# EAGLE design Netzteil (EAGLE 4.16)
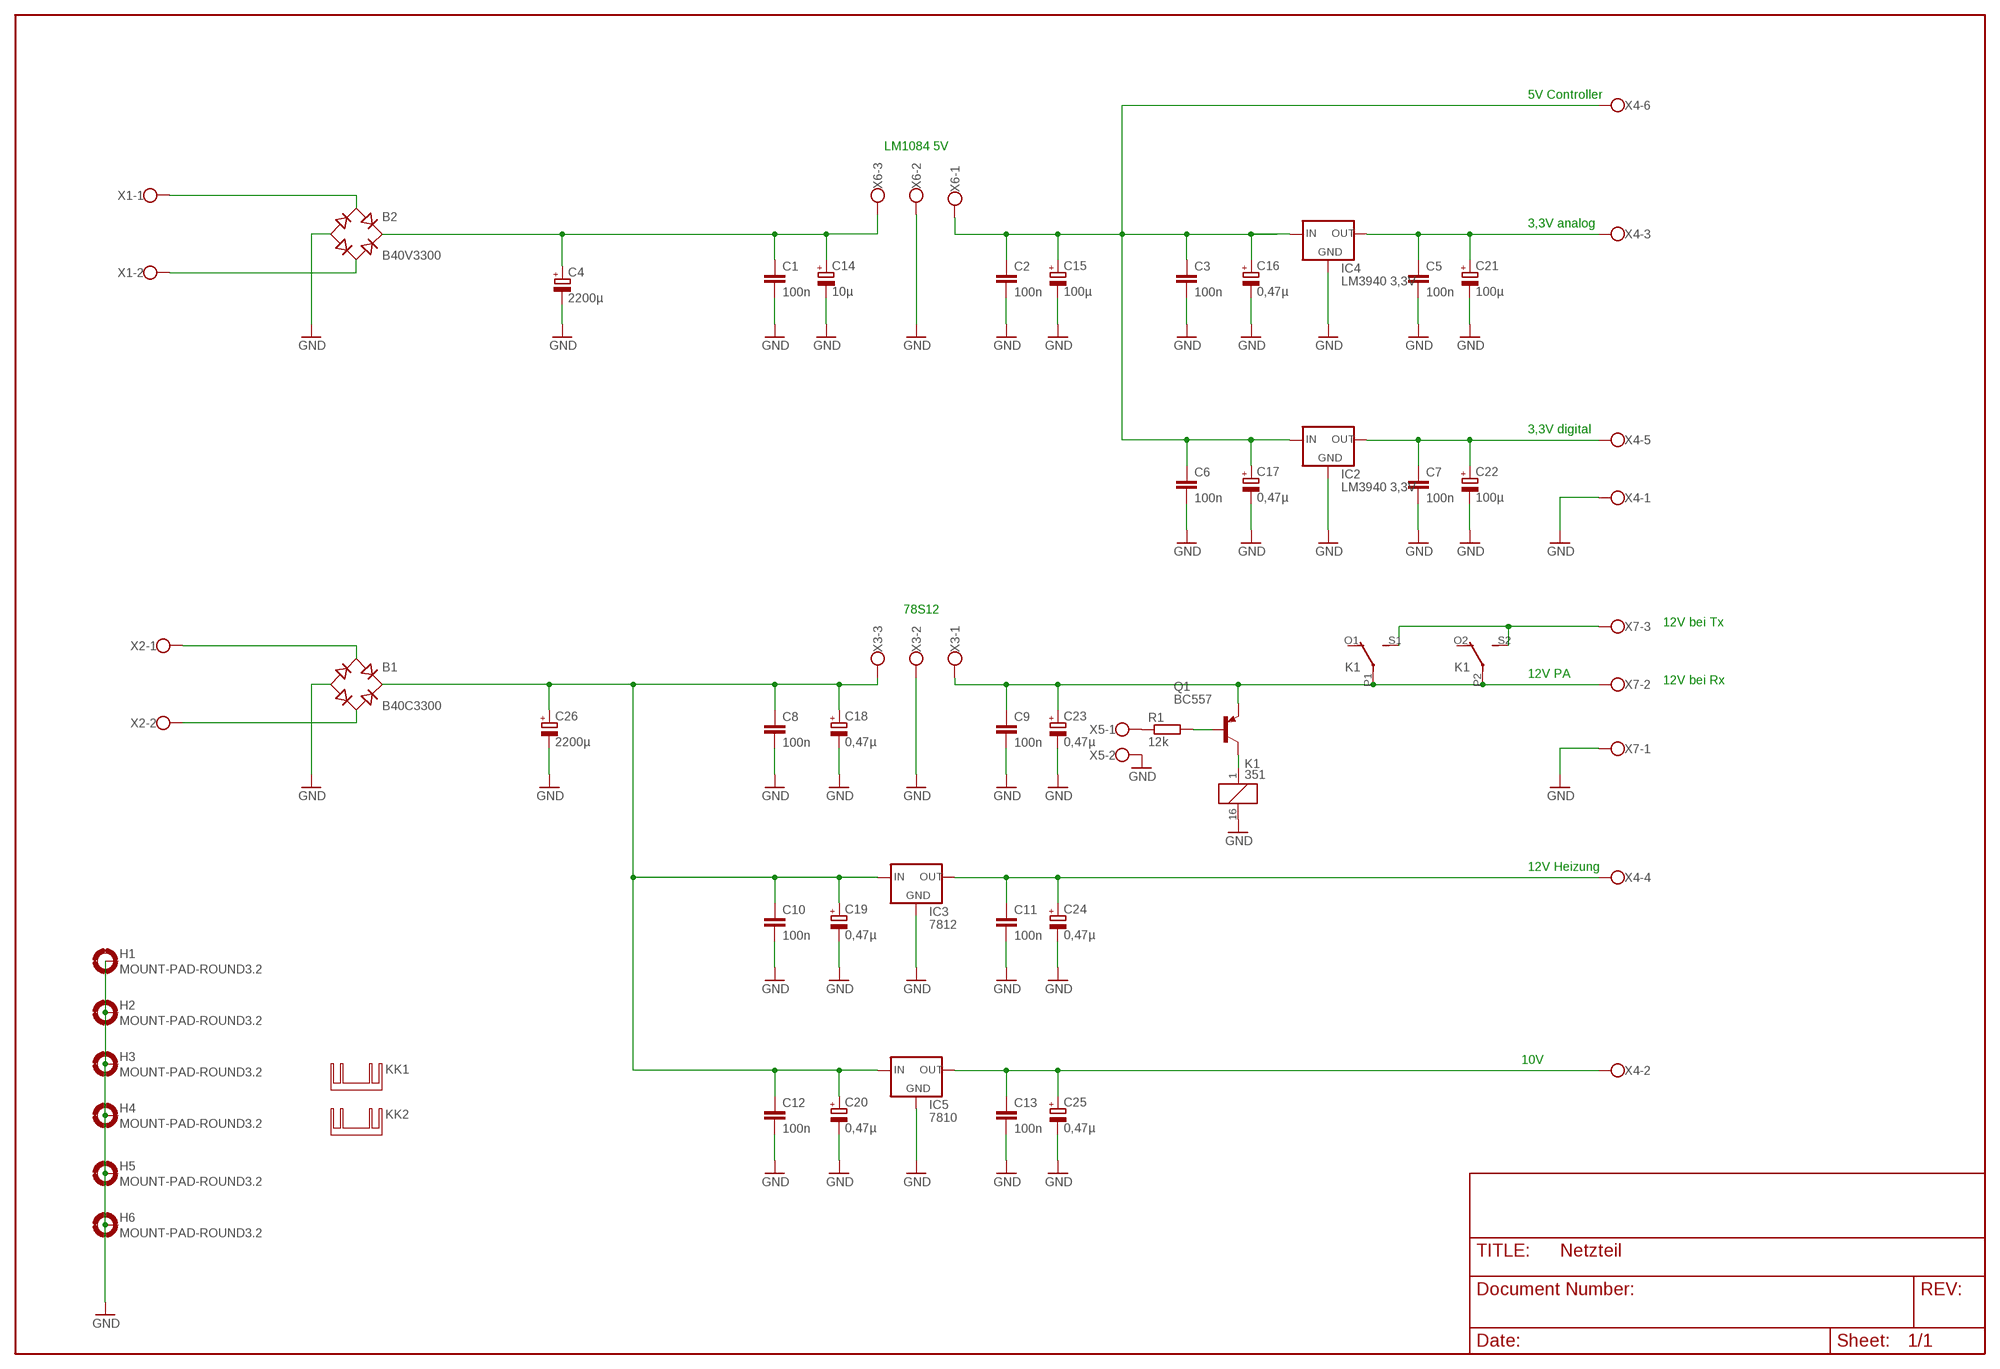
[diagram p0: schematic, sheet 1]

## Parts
B1  B40C3300  RECTIFIER-FB100  [FB100]
B2  B40V3300  RECTIFIER-FB100  [FB100]
C1  100n  C-EUC0805K  [C0805K]
C2  100n  C-EUC0805K  [C0805K]
C3  100n  C-EUC0805K  [C0805K]
C4  2200µ  CPOL-EUE7.5-18  [E7,5-18]
C5  100n  C-EUC0805K  [C0805K]
C6  100n  C-EUC0805K  [C0805K]
C7  100n  C-EUC0805K  [C0805K]
C8  100n  C-EUC0805K  [C0805K]
C9  100n  C-EUC0805K  [C0805K]
C10  100n  C-EUC0805K  [C0805K]
C11  100n  C-EUC0805K  [C0805K]
C12  100n  C-EUC0805K  [C0805K]
C13  100n  C-EUC0805K  [C0805K]
C14  10µ  CPOL-EUD/7343-31W  [D/7343-31W]
C15  100µ  CPOL-EUD/7343-31W  [D/7343-31W]
C16  0,47µ  CPOL-EUA/3216-18W  [A/3216-18W]
C17  0,47µ  CPOL-EUA/3216-18W  [A/3216-18W]
C18  0,47µ  CPOL-EUA/3216-18W  [A/3216-18W]
C19  0,47µ  CPOL-EUA/3216-18W  [A/3216-18W]
C20  0,47µ  CPOL-EUA/3216-18W  [A/3216-18W]
C21  100µ  CPOL-EUD/7343-31W  [D/7343-31W]
C22  100µ  CPOL-EUD/7343-31W  [D/7343-31W]
C23  0,47µ  CPOL-EUA/3216-18W  [A/3216-18W]
C24  0,47µ  CPOL-EUA/3216-18W  [A/3216-18W]
C25  0,47µ  CPOL-EUA/3216-18W  [A/3216-18W]
C26  2200µ  CPOL-EUE7.5-18  [E7,5-18]
H1  MOUNT-PAD-ROUND3.2  [3,2-PAD]
H2  MOUNT-PAD-ROUND3.2  [3,2-PAD]
H3  MOUNT-PAD-ROUND3.2  [3,2-PAD]
H4  MOUNT-PAD-ROUND3.2  [3,2-PAD]
H5  MOUNT-PAD-ROUND3.2  [3,2-PAD]
H6  MOUNT-PAD-ROUND3.2  [3,2-PAD]
IC2  LM3940 3,3V  78MXXS  [78MXXS]
IC3  7812  78MXXS  [78MXXS]
IC4  LM3940 3,3V  78MXXS  [78MXXS]
IC5  7810  78MXXS  [78MXXS]
K1  351  [351]
KK1  50X50X28  [50X50X28]
KK2  50X50X28  [50X50X28]
Q1  BC557  [TO92]
R1  12k  R-EU_0207/10  [0207/10]
X1  W237-02P  [W237-132]
X2  W237-02P  [W237-132]
X3  W237-3E  [W237-3E]
X4  W237-06P  [W237-6P]
X5  W237-02P  [W237-132]
X6  W237-3E  [W237-3E]
X7  W237-03P  [W237-133]

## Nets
3V3_ANALOG: C5.1 C21.+ IC4.OUT X4.3
3V3_DIGITAL: C7.1 C22.+ IC2.OUT X4.5
5V: C2.1 C3.1 C6.1 C15.+ C16.+ C17.+ IC2.IN IC4.IN X4.6 X6.1
10V: C13.1 C25.+ IC5.OUT X4.2
12V_HEIZUNG: C11.1 C24.+ IC3.OUT X4.4
12V_PA: C9.1 C23.+ K1.P1(2:P) K1.P2(3:P) Q1.1(E) X3.1 X7.2
GND: B1.- B2.- C1.2 C2.2 C3.2 C4.- C5.2 C6.2 C7.2 C8.2 C9.2 C10.2 C11.2 C12.2 C13.2 C14.- C15.- C16.- C17.- C18.- C19.- C20.- C21.- C22.- C23.- C24.- C25.- C26.- H1.B3,2(MOUNT) H2.B3,2(MOUNT) H3.B3,2(MOUNT) H4.B3,2(MOUNT) H5.B3,2(MOUNT) H6.B3,2(MOUNT) IC2.GND IC3.GND IC4.GND IC5.GND K1.16 X3.2 X4.1 X5.2 X6.2 X7.1
N$1: K1.S1(2:S) K1.S2(3:S) X7.3
N$2: K1.1 Q1.3(C)
N$3: Q1.2(B) R1.2
N$4: B2.AC1 X1.1
N$5: B2.AC2 X1.2
N$6: B1.AC1 X2.1
N$7: R1.1 X5.1
N$8: B1.+ C8.1 C10.1 C12.1 C18.+ C19.+ C20.+ C26.+ IC3.IN IC5.IN X3.3
N$10: B1.AC2 X2.2
VIN: B2.+ C1.1 C4.+ C14.+ X6.3
Unconnected: K1.O1(2:O) K1.O2(3:O)

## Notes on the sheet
- 5V Controller
- LM1084 5V
- 3,3V analog
- 3,3V digital
- 78S12
- 12V bei Tx
- 12V PA
- 12V bei Rx
- 12V Heizung
- 10V

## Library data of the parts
B1 B2 = rectifier:RECTIFIER-: Rectifier
C1-C3 C5-C13 = rcl:C-EU: CAPACITOR, European symbol
C4 C14-C26 = rcl:CPOL-EU: POLARIZED CAPACITOR, European symbol
H1-H6 = holes:MOUNT-PAD-ROUND: MOUNTING PAD, round
IC2-IC5 = v-reg:78MXXS: VOLTAGE REGULATOR
K1 = relay:351: RELAY 2 x switch, Omron
KK1 KK2 = heatsink:50X50X28
Q1 = transistor-pnp:BC557: PNP Transistor
R1 = rcl:R-EU_: RESISTOR, European symbol
X1 X2 X5 = con-wago-508:W237-02P: WAGO SREW CLAMP
X3 X6 = con-wago-508:W237-3E: WAGO SREW CLAMP
X4 = con-wago-508:W237-06P: WAGO SREW CLAMP
X7 = con-wago-508:W237-03P: WAGO SREW CLAMP

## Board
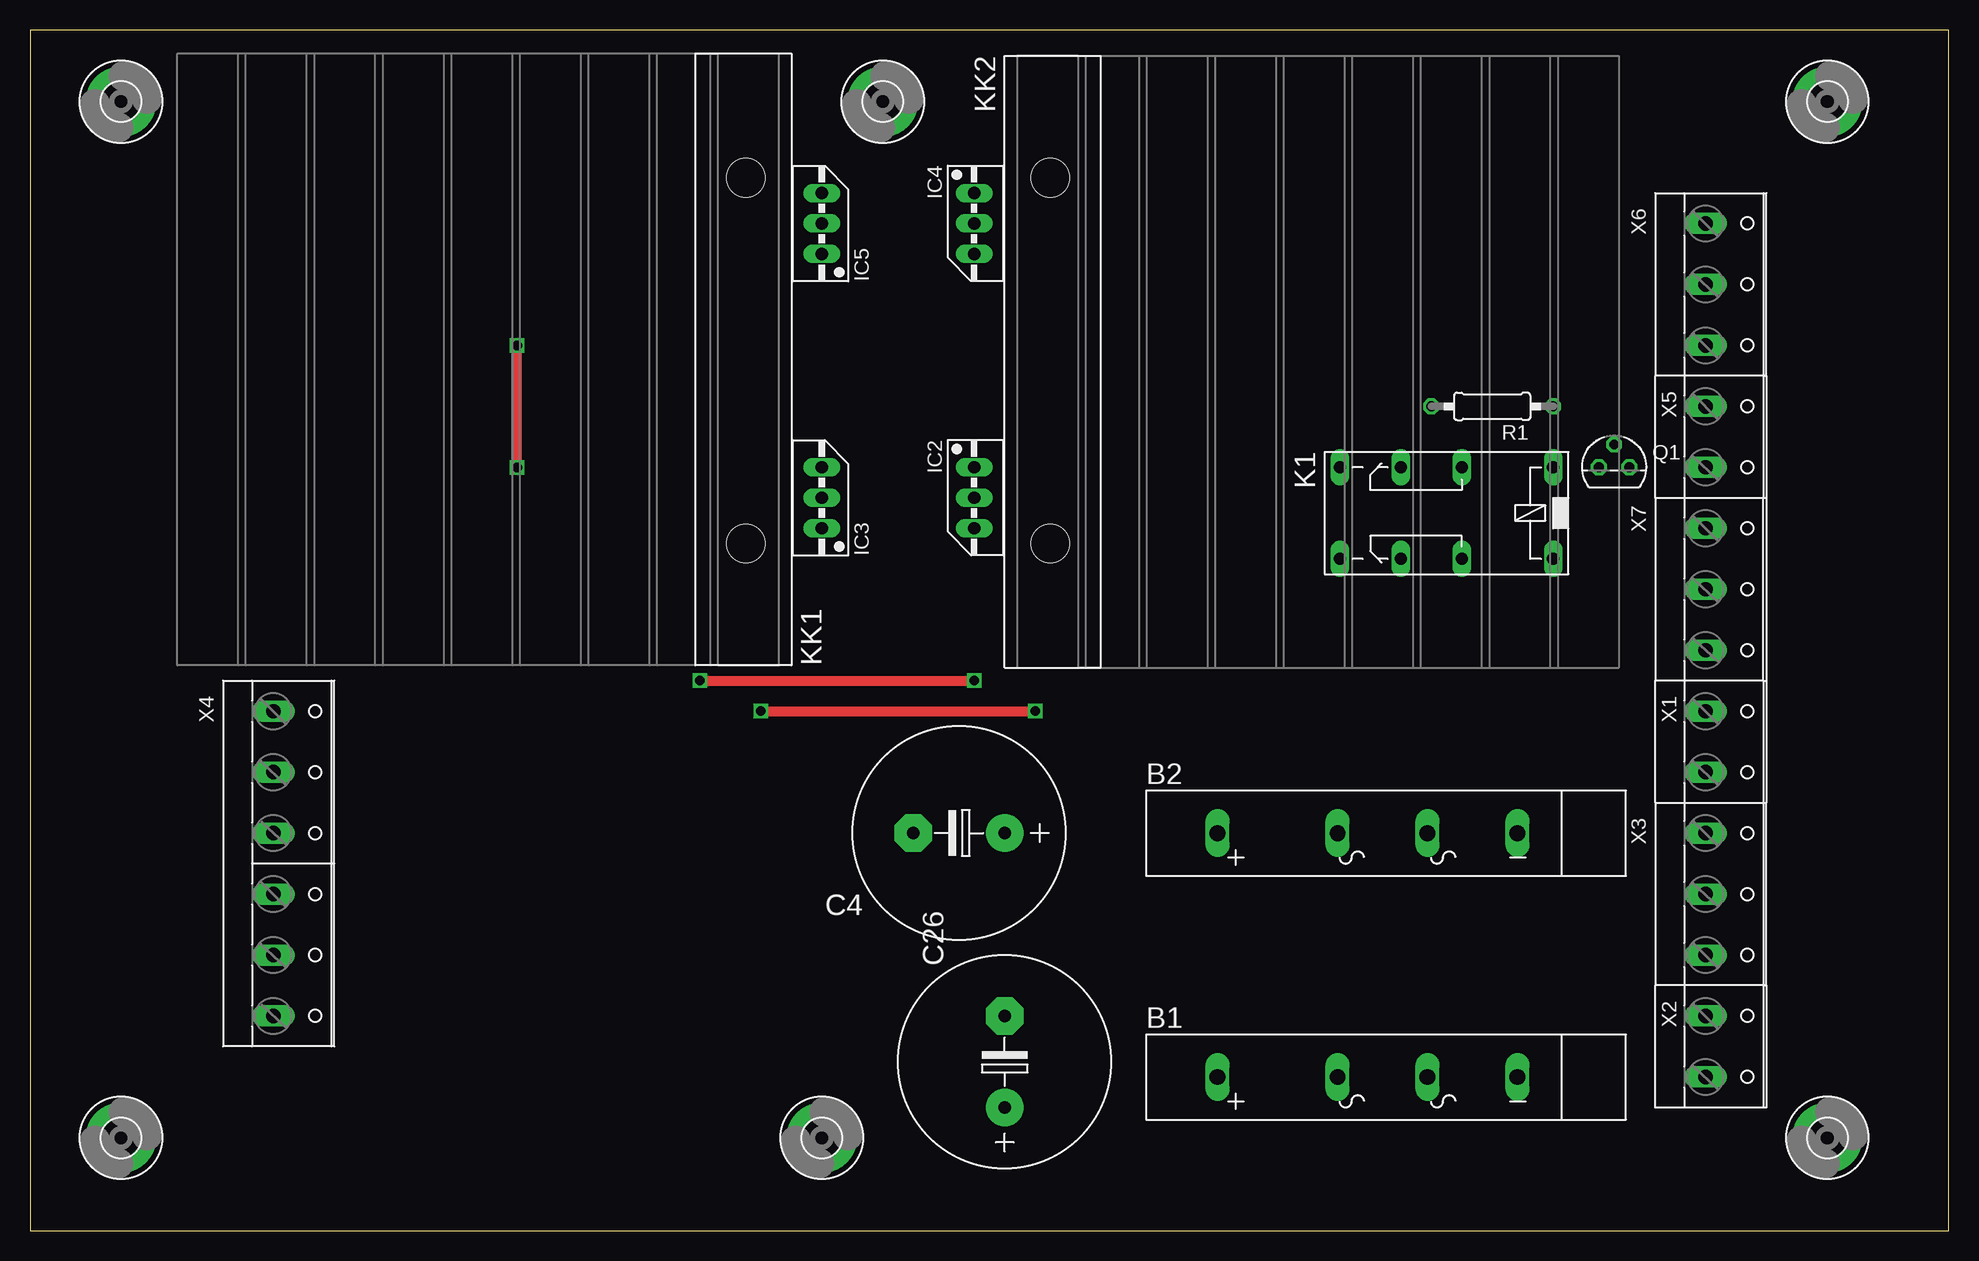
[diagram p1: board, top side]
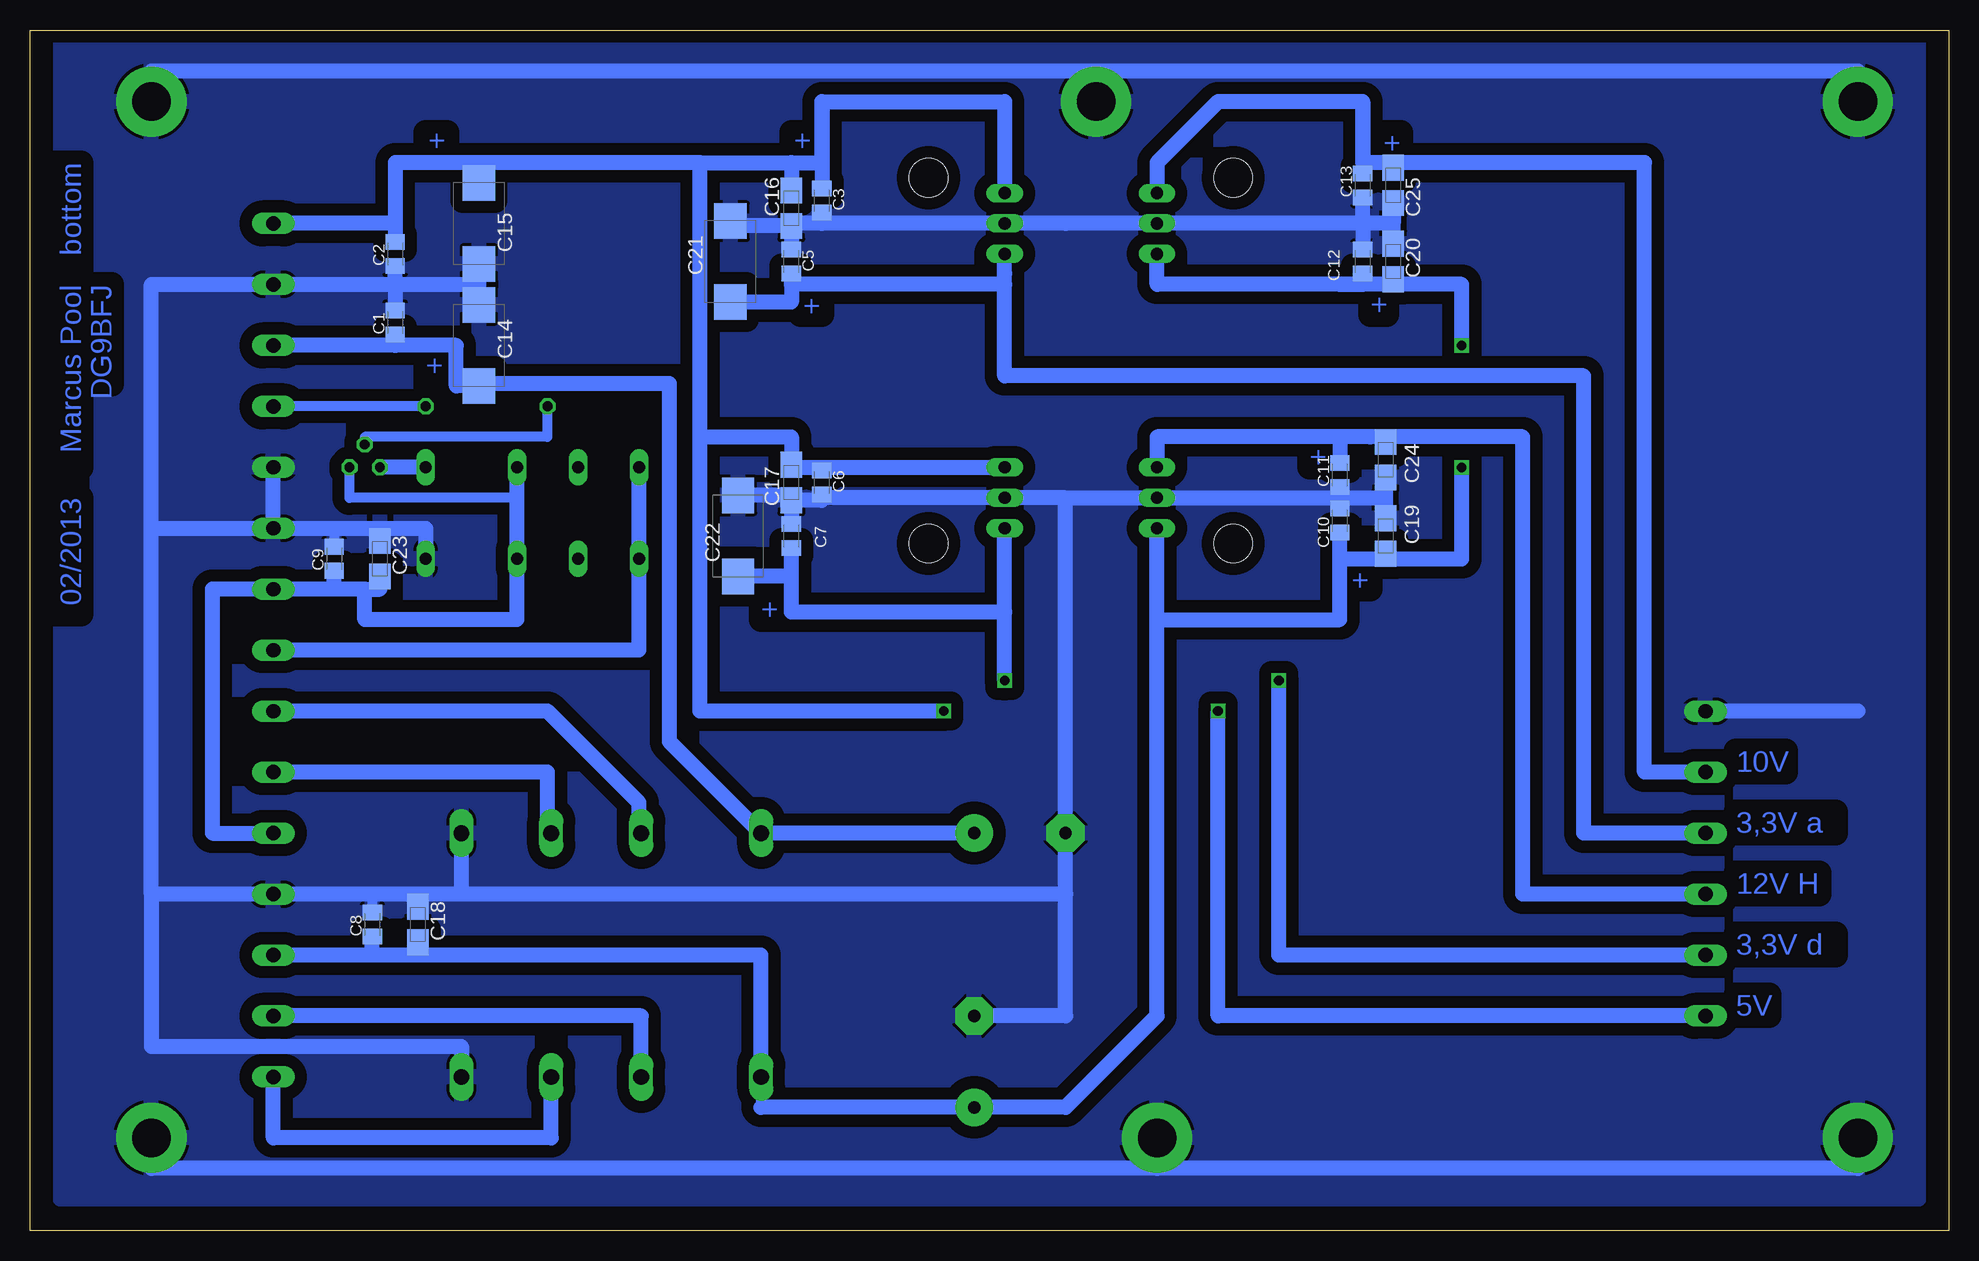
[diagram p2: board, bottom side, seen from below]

Size 159.94 x 100.07 mm. Coordinates in mm from the lower left corner, seen from the top.
Outline: 0,0 159.94,0 159.94,100.07 0,100.07 0,0
Copper layers (1*16): Top 0.035mm / dielectric 1.5mm / Bottom 0.035mm
Design rules "default": minimum track width 10mil, minimum drill 24mil, track to track 8mil, track to pad 8mil, pad to pad 8mil, via to via 8mil, smd to smd 8mil, copper to edge 40mil, drill to drill 8mil, minimum pad ring 10mil, minimum via ring 8mil, stop-mask expansion 4mil, vias tented up to drill 0mil, thermal gap 10mil

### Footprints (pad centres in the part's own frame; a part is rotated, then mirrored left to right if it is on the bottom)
FB100 = drill 1.321 long: + -14,0; - 10.994,0; AC1 -3.992,0; AC2 3.501,0
C0805K = smd 1.3 x 1.6: 1 -1,0; 2 1,0
E7,5-18 = drill 1.016 pad 3.15 round: + -3.81,0 | drill 1.016 pad 3.15 octagon: - 3.81,0
D/7343-31W = smd 2.95 x 2.7: + 3.375,0; - -3.375,0
A/3216-18W = smd 2.15 x 1.8: + 1.475,0; - -1.475,0
3,2-PAD = drill 3.2 pad 5.842 round: B3,2 0,0
78MXXS = drill 1.016 long: GND 0,-2.54; IN -2.54,-2.54; OUT 2.54,-2.54
351 = drill 1.016 long: 1 -3.81,-3.81; 16 -3.81,3.81; O1 8.89,-3.81; O2 8.89,3.81; P1 3.81,-3.81; P2 3.81,3.81; S1 13.97,-3.81; S2 13.97,3.81
50X50X28 = hole 3.2: -15.24,3.81; 15.24,3.81
TO92 = drill 0.813 octagon: 1 1.27,0; 2 0,1.905; 3 -1.27,0
0207/10 = drill 0.813 octagon: 1 -5.08,0; 2 5.08,0
W237-132 = drill 1.194 long: 1 -2.54,-0.635; 2 2.54,-0.635
W237-3E = drill 1.194 long: 1 -5.08,-0.635; 2 0,-0.635; 3 5.08,-0.635
W237-6P = drill 1.194 long: 1 -12.7,-0.635; 2 -7.62,-0.635; 3 -2.54,-0.635; 4 2.54,-0.635; 5 7.62,-0.635; 6 12.7,-0.635
W237-133 = drill 1.194 long: 1 -5.08,-0.635; 2 0,-0.635; 3 5.08,-0.635

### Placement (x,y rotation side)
B1  112.99,12.82 0 top
B2  112.99,33.14 0 top
C1  129.5,75.69 90 bottom
C2  129.5,81.4 270 bottom
C3  93.94,85.85 270 bottom
C4  77.43,33.14 180 top
C5  96.48,80.77 90 bottom
C6  93.94,62.35 270 bottom
C7  96.48,57.91 90 bottom
C8  131.41,25.52 90 bottom
C9  134.58,56 90 bottom
C10  50.76,59.18 90 bottom
C11  50.76,62.99 270 bottom
C12  48.86,80.77 90 bottom
C13  48.86,87.12 270 bottom
C14  122.52,73.78 270 bottom
C15  122.52,83.94 90 bottom
C16  96.48,85.21 90 bottom
C17  96.48,62.35 90 bottom
C18  127.6,25.52 270 bottom
C19  46.95,57.91 270 bottom
C20  46.32,80.77 270 bottom
C21  101.56,80.77 270 bottom
C22  100.93,57.91 270 bottom
C23  130.77,56 270 bottom
C24  46.95,64.26 90 bottom
C25  46.32,87.12 90 bottom
C26  81.24,14.09 90 top
H1  7.58,94.1 0 top
H2  149.82,7.74 0 top
H3  149.82,94.1 0 top
H4  7.58,7.74 0 top
H5  66,7.74 0 top
H6  71.08,94.1 0 top
IC2  81.24,61.08 270 top
IC3  63.46,61.08 90 top
IC4  81.24,83.94 270 top
IC5  63.46,83.94 90 top
K1  123.15,59.81 180 top
KK1  63.46,72.51 90 top
KK2  81.24,72.51 270 top
Q1  132.04,63.62 0 top
R1  121.88,68.7 180 top
X1  140.3,40.76 270 top
X2  140.3,15.36 270 top
X3  140.3,28.06 270 top
X4  20.92,30.6 270 top
X5  140.3,66.16 270 top
X6  140.3,78.86 270 top
X7  140.3,53.46 270 top

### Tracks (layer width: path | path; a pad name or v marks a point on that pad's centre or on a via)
3V3_ANALOG
  Bottom 0.813: 78.7,79.77 78.7,78.86
  Bottom 1.27: IC4.OUT 78.7,79.77 78.7,71.24 30.44,71.24 30.44,33.14 X4.3 | C21.+ 96.48,77.39 96.48,78.86 | 96.48,78.86 C5.1 | 78.7,78.86 96.48,78.86
3V3_DIGITAL  (via drill 0.8)
  Top 0.813: v55.84,45.84 v78.7,45.84
  Bottom 1.27: C22.+ 96.48,54.53 96.48,51.56 | 96.48,51.56 C7.1 | 78.7,51.56 96.48,51.56 | v78.7,45.84 78.7,51.56 | 78.7,51.56 IC2.OUT | X4.5 55.84,22.98 v55.84,45.84
5V  (via drill 0.8)
  Top 0.813: v60.92,43.3 v83.78,43.3
  Bottom 0.406: 93.94,63.62 C6.1 | 96.48,63.62 C17.+
  Bottom 0.813: IC4.IN 78.7,87.75 | IC2.IN 93.94,63.62 96.48,63.62 | 129.5,87.32 129.5,86.48 129.5,87.75 | 129.5,83.94 129.5,82.67 C2.1 | 121.88,89.02 121.88,87.75 | 121.88,89.02 121.88,86.48 | C15.+ 121.88,87.32 121.88,89.02
  Bottom 1.27: IC2.IN 96.48,63.62 96.48,66.16 104.1,66.16 | 129.5,83.94 X6.1 | X4.6 60.92,17.9 v60.92,43.3 | v83.78,43.3 104.1,43.3 104.1,66.16 | 104.1,66.16 104.1,89.02 | 104.1,89.02 121.88,89.02 129.5,89.02 129.5,86.48 129.5,82.67 | IC4.IN 78.7,94.1 93.94,94.1 | 104.1,89.02 96.48,89.02 | 96.48,89.02 93.94,89.02 93.94,94.1 | 93.94,94.1 C3.1 | 96.48,89.02 C16.+
10V
  Bottom 0.813: 46.32,89.02 C25.+
  Bottom 1.27: 48.22,89.02 46.32,89.02 45.68,89.02 | 48.86,94.1 48.86,89.66 | 48.86,89.02 C13.1 | IC5.OUT 66,89.02 60.92,94.1 48.86,94.1 | X4.2 25.36,38.22 25.36,89.02 45.68,89.02 | 48.86,89.02 48.86,94.1 | 45.68,89.02 48.86,89.02
12V_HEIZUNG
  Bottom 0.813: 48.22,66.16 46.95,66.16
  Bottom 1.27: 46.95,66.16 C24.+ | 50.76,66.16 48.22,66.16 35.52,66.16 35.52,28.06 X4.4 | 50.76,66.16 66,66.16 IC3.OUT | 50.76,66.16 C11.1
12V_PA
  Bottom 0.813: Q1.1 133.31,61.08 119.34,61.08
  Bottom 1.27: C23.+ 130.77,53.46 132.04,53.46 | 132.04,53.46 134.58,53.46 | 134.58,53.46 C9.1 | X3.1 144.74,33.14 144.74,53.46 X7.2 134.58,53.46 | K1.P1 119.34,61.08 K1.P2 119.34,50.92 132.04,50.92 132.04,53.46
GND
  Bottom 0.813: 73.62,61.08 IC2.GND | 96.48,83.94 C16.- | C17.- 96.48,61.28 | 101.56,83.74 C21.- | C2.2 129.5,78.23 | 122.52,76.32 C14.- 122.52,78.86 | C23.- 130.77,58.54 132.04,58.54 134.58,58.54 C9.2 | C19.- 46.95,59.18 | 46.95,61.08 C24.- | 127.6,28.06 C18.- | 131.41,28.06 C8.2 | 73.62,32.51 C4.- | 149.82,5.2 H2.B3,2
  Bottom 1.27: 149.82,28.06 X3.2 131.41,28.06 127.6,28.06 123.99,28.06 | 149.82,28.06 149.82,15.36 123.99,15.36 B1.- | 149.82,58.54 149.82,78.86 X6.2 129.5,78.86 | 149.82,28.06 149.82,58.54 | 73.62,61.08 IC3.GND 50.76,61.08 | 73.62,17.9 C26.- | 73.62,17.9 73.62,32.51 73.62,61.08 | C5.2 C16.- 101.56,83.74 | 93.94,83.94 96.48,83.94 | 93.94,83.94 C3.2 | 93.94,83.94 IC4.GND 73.62,83.94 IC5.GND 48.86,83.94 | 73.62,61.08 93.94,61.08 | 93.94,61.08 C6.2 | 93.94,61.08 93.94,60.88 C17.- C7.2 | 96.48,61.28 C22.- | 129.5,78.86 C2.2 | 129.5,78.86 129.5,78.23 C1.2 | 129.5,78.86 122.52,78.86 C15.- | C20.- C25.- 46.32,83.94 48.86,83.94 | 48.86,83.94 C13.2 | C24.- C19.- | 50.76,61.08 46.95,61.08 | 48.86,83.94 C12.2 | 123.99,28.06 B2.- | 7.58,43.3 X4.1 | 50.76,61.08 C10.2 | 50.76,61.08 C11.2 | 73.62,17.9 73.62,28.06 123.99,28.06 | X7.1 132.04,58.54 126.96,58.54 K1.16 | 149.82,58.54 X7.1 | X7.1 X5.2 | H4.B3,2 7.58,5.2 66,5.2 | 66,5.2 H5.B3,2 | 66,5.2 149.82,5.2 | H1.B3,2 7.58,96.64 71.08,96.64 149.82,96.64 H3.B3,2
  pour Bottom (isolate 1.016): 2.5,2.66 2.5,99.18 157.44,99.18 157.44,2.66
N$1
  Bottom 1.27: X7.3 109.18,48.38 K1.S2 K1.S1
N$2
  Bottom 1.27: K1.1 Q1.3
N$3
  Bottom 0.813: Q1.2 132.04,66.16 116.8,66.16 R1.2
N$4
  Bottom 0.813: B2.AC1 109.18,33.14
  Bottom 1.27: X1.1 116.8,43.3 109.18,35.68 109.18,33.14
N$5
  Bottom 0.813: B2.AC2 116.8,33.14
  Bottom 1.27: X1.2 116.8,38.22 116.8,33.14
N$6
  Bottom 1.27: B1.AC1 109,17.9 X2.1
N$7
  Bottom 0.813: R1.1 X5.1
N$8  (via drill 0.8)
  Top 0.813: v40.6,63.62 v40.6,73.78
  Bottom 0.813: 46.32,79.5 C20.+ 46.32,78.86 | 46.95,56 C19.+ | 126.96,22.98 127.6,22.98 | 99.02,10.28 B1.+ 99.02,12.82 99.02,10.28
  Bottom 1.016: 132.04,22.98 131.41,22.98
  Bottom 1.27: 99.02,10.28 C26.+ 73.62,10.28 66,17.9 66,50.92 | 66,50.92 IC3.IN | 66,50.92 50.76,50.92 | 50.76,50.92 50.76,56 48.22,56 | 48.22,56 46.95,56 | 50.76,50.92 C10.1 | X3.3 132.04,22.98 126.96,22.98 99.02,22.98 99.02,12.82 | 127.6,22.98 C18.+ | 131.41,22.98 C8.1 | v40.6,73.78 40.6,78.86 45.68,78.86 | 45.68,78.86 50.76,78.86 | 50.76,78.86 66,78.86 IC5.IN | 45.68,78.86 46.32,78.86 | C12.1 48.86,78.86 50.76,78.86 | v40.6,63.62 40.6,56 48.22,56
N$10
  Bottom 1.27: X2.2 139.66,7.74 116.49,7.74 B1.AC2
VIN
  Bottom 0.813: 122.52,70.61 C14.+ | 99.02,33.14 B2.+
  Bottom 1.27: C14.+ 124.42,70.41 124.42,73.78 129.5,73.78 | 129.5,73.78 C1.1 | 129.5,73.78 X6.3 | 122.52,70.61 106.64,70.61 106.64,40.76 99.02,33.14 C4.+

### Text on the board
Bottom: + | + | + | bottom | DG9BFJ | Marcus Pool | + | + | + | + | 02/2013 | + | + | 10V | 3,3V a | 12V H | 3,3V d | 5V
